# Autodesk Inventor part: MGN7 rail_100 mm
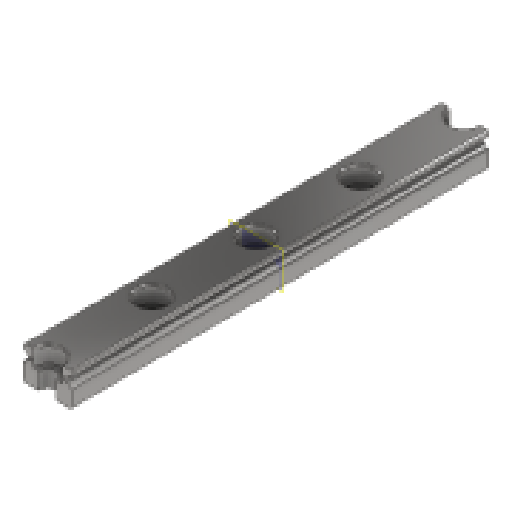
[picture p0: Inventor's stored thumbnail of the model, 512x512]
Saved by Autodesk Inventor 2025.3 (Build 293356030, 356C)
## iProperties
Created: 2019-04
Part Number: MGN7 rail_100 mm
Material: Generico
Document SubType Name: Modeling
Designer: R5800u
Density: 1 g/cm^3
Appearance: Acciaio - Lucido
Author: R5800u
Revision Number: ANY
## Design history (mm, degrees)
node "LPattern1"
sketch "Schizzo3"
  geometry: L1 (-3.329, -12.115)-(9.929, -12.115); L2 (9.929, -12.115)-(9.929, -72.115); L3 (9.929, -72.115)-(-3.329, -72.115); L4 (-3.329, -72.115)-(-3.329, -12.115); L5 (-3.329, -12.115)-(9.929, -72.115); L6 (9.929, -12.115)-(-3.329, -72.115); L7 (3.3, -35)-(3.3, -50); L8 (-3.329, -12.115)-(9.929, -12.115); L9 (9.929, -12.115)-(9.929, 3.942); L10 (9.929, 3.942)-(-3.329, 3.942); L11 (-3.329, 3.942)-(-3.329, -12.115); L12 (-3.329, -72.115)-(9.929, -72.115); L13 (9.929, -72.115)-(9.929, -103.308); L14 (9.929, -103.308)-(-3.329, -103.308); L15 (-3.329, -103.308)-(-3.329, -72.115); C1 r 1.4 at (3.3, -35) reference; C2 r 1.2 at (3.3, -50) reference; 4 further points
  constraints: 30 end point, 6 parallel, 3 horizontal, 3 perpendicular, 2 midpoint, 1 point on line, 1 vertical
  dimensions: "d4" = 60 distance of L1.end L2.end
extrude "Estrusione3" cut sketch "Schizzo3" extent not by distance; stored distance "d5" = 0; taper "d6" = 0 deg
node "Asse di lavoro1"
  node "Piano di lavoro2"
node "Solido1"
